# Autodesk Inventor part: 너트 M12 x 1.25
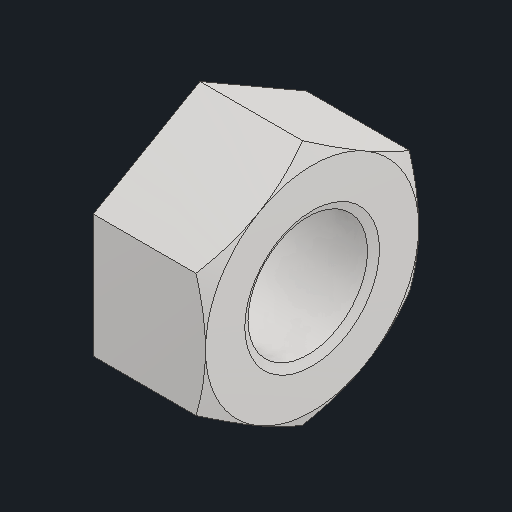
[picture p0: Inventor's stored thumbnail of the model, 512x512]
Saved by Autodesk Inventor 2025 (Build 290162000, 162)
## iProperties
Created: 2025-08
Part Number: 너트 M12 x 1.25
Material: 스테인리스강
Description: 6각 너트
Document SubType Name: Modeling
Designer: infra023
Density: 8.08 g/cm^3
Appearance: 기본값
Author: jhkim
Sending System: Autodesk Inventor 2026
Preprocessor: ST-DEVELOPER v20.1
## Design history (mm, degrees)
feature "Solid1"
node "솔리드1"
